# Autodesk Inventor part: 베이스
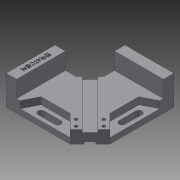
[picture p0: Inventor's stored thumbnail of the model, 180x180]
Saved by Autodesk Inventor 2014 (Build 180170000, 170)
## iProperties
Created: 2019-04
Part Number: 베이스
Material: Generic
Document SubType Name: Modeling
Designer: kh
Density: 1 g/cm^3
Appearance: Default
Author: kh
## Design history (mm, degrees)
sketch "Sketch1"
  geometry: L1 (-60, 60)-(60, 60); L2 (60, 60)-(60, -60); L3 (60, -60)-(-60, -60); L4 (-60, -60)-(-60, 60); L5 (-60, 60)-(60, -60); L6 (60, 60)-(-60, -60); L7 (60, -60)-(45.858, -45.858); L8 (45.858, -45.858)-(31.716, -60); L9 (45.858, -45.858)-(60, -31.716); 1 further point
  constraints: 18 end point, 3 equal length, 3 point on line, 2 midpoint, 2 perpendicular, 1 horizontal
  dimensions: "d5" = 120 distance of L2.end L3.end; "d6" = 120 distance of L1.end L2.end; "d7" = 20 distance of L2.end L7.end
extrude "Extrusion1" new body sketch "Sketch1" distance "d8" = 18; taper "d9" = 0 deg
sketch "Sketch2"
  geometry: L1 (-60, 60)-(-60, -60) reference; L2 (31.716, -60)-(60, -31.716) reference; L3 (60, 60)-(-60, 60) reference; L4 (45.858, -45.858)-(-19.903, 19.903); L5 (-60, 60)-(-60, 10); L6 (-60, 60)-(-10, 60); L7 (-19.903, 19.903)-(-44.384, -4.578); L8 (-19.903, 19.903)-(6.453, 46.259); L9 (-60, 10)-(-29.806, 10); L10 (-10, 60)-(-10, 29.806); 1 further point
  constraints: 14 end point, 4 point on line, 3 perpendicular, 1 collinear, 1 midpoint, 1 parallel
  dimensions: "d10" = 93 distance of L4.start L4.end; "d11" = 50 distance of L1.start L5.end; "d12" = 50 distance of L1.start L6.end
extrude "Extrusion2" cut sketch "Sketch2" stored distance "d13" = 18; taper "d14" = 0 deg
sketch "Sketch3"
  geometry: L1 (-29.806, 10)-(-60, 10) reference; L2 (60, -31.716)-(60, 60) reference; L3 (-60, -60)-(-45, -60); L4 (-45, -60)-(-45, 10); L5 (-45, 10)-(-60, 10); L6 (-60, 10)-(-60, -60); L7 (-10, 60)-(60, 60); L8 (60, 60)-(60, 45); L9 (60, 45)-(-10, 45); L10 (-10, 45)-(-10, 60); 1 further point
  constraints: 16 end point, 4 parallel, 2 horizontal, 2 perpendicular, 2 point on line
  dimensions: "d15" = 15 distance of L5.end L4.end; "d16" = 15 distance of L7.end L8.end
extrude "Extrusion3" join sketch "Sketch3" distance "d17" = 24; taper "d18" = 0 deg
sketch "Sketch4"
  geometry: L1 (31.716, -60)-(60, -31.716) reference; L2 (-10, 29.806)-(-29.806, 10) reference; L3 (-25.56, 14.246)-(40.201, -51.515); L4 (-14.246, 25.56)-(51.515, -40.201); L5 (0, 0)-(45.858, -45.858); L6 (-25.56, 14.246)-(-14.246, 25.56); L7 (40.201, -51.515)-(51.515, -40.201)
  constraints: 10 end point, 4 point on line, 2 perpendicular, 1 collinear, 1 midpoint, 1 parallel, 1 other
  dimensions: "d19" = 16 distance of L3.end L4.end
extrude "Extrusion4" cut sketch "Sketch4" distance "d20" = 3.5; taper "d21" = 0 deg
sketch "Sketch5"
  geometry: L1 (-31.716, -60)-(-60, -31.716) reference; L2 (29.806, 10)-(10, 29.806) reference; L3 (0, 0)-(-45.858, -45.858); L4 (-50.101, -41.615)-(15.66, 24.146); L5 (-41.615, -50.101)-(24.146, 15.66); L6 (15.66, 24.146)-(24.146, 15.66); L7 (-50.101, -41.615)-(-41.615, -50.101)
  constraints: 10 end point, 4 point on line, 2 collinear, 2 perpendicular, 1 midpoint, 1 other
  dimensions: "d22" = 12 distance of L4.start L5.start
extrude "Extrusion5" cut sketch "Sketch5" distance "d23" = 3; taper "d24" = 0 deg
sketch "Sketch6"
  geometry: L1 (-45, -60)-(31.716, -60) reference; L2 (31.716, -60)-(40.201, -51.515) reference; L3 (-45, -60)-(-40, -60); L4 (-40, -60)-(-30, -40); L5 (-30, -40)-(7.321, -40); L6 (31.716, -60)-(11.716, -40); L7 (-30, -40)-(11.716, -40); L8 (-60, 10)-(-60, -60) reference; L9 (-45, 10)-(-60, 10) reference; L10 (-60, 10)-(-60, -60) reference; L11 (-60, -60)-(-45, -60) reference; L12 (-45, -60)-(-45, 10) reference; L13 (-60, -60)-(-45, -60) reference; L14 (-20, -50)-(4, -50); L15 (-20, -52.25)-(4, -52.25); L16 (4, -47.75)-(-20, -47.75); L17 (-9.142, -40)-(-9.142, -60); A1 r 2.25 centre (-20, -50) between (-20, -47.75) and (-20, -52.25); A2 r 2.25 centre (4, -50) between (4, -52.25) and (4, -47.75); 2 further points
  constraints: 20 end point, 4 point on circle, 4 tangent, 3 parallel, 2 centre point, 2 midpoint, 2 perpendicular, 2 point on line, 1 collinear
  dimensions: "d25" = 5 distance of L1.start L3.end; "d26" = 30 horizontal distance of L4.end L8.end; "d30" = 20 vertical distance of L4.end L3.end; "d31" = 24 distance of L14.start L14.end; "d32" = 4.5 diameter of A2; "d33" = 40 horizontal distance of L14.start L8.end; "d34" = 10 vertical distance of L8.end L14.start
extrude "Extrusion6" cut sketch "Sketch6" distance "d35" = 10; taper "d36" = 0 deg
sketch "Sketch7"
  geometry: L1 (4, -47.75)-(-20, -47.75) reference; L2 (-20, -52.25)-(4, -52.25) reference; A1 r 2.25 centre (4, -50) between (4, -52.25) and (4, -47.75) reference; A2 r 2.25 centre (-20, -50) between (-20, -47.75) and (-20, -52.25) reference; 1 further point
extrude "Extrusion7" cut sketch "Sketch7" stored distance "d37" = 10; taper "d38" = 0 deg
sketch "Sketch8"
  geometry: L1 (60, -31.716)-(60, 45) reference; L2 (-10, 45)-(-10, 29.806) reference; L3 (-10, 29.806)-(-14.246, 25.56) reference; L4 (60, -31.716)-(40, -11.716); L5 (40, -11.716)-(40, 30); L6 (40, 30)-(60, 40); L7 (60, 45)-(60, 60) reference; L8 (60, 60)-(-10, 60) reference; L9 (-10, 60)-(-10, 45) reference; L10 (-10, 45)-(60, 45) reference; 1 further point
  constraints: 6 end point, 1 parallel, 1 perpendicular, 1 point on line
  dimensions: "d39" = 20 distance of L7.end L6.end; "d40" = 30 vertical distance of L5.end L7.end; "d41" = 20 horizontal distance of L5.end L7.end
extrude "Extrusion8" cut sketch "Sketch8" distance "d42" = 10; taper "d43" = 0 deg
sketch "Sketch9"
  geometry: L1 (60, 40)-(60, -31.716) reference; L2 (50, -4)-(50, 20); L3 (52.25, -4)-(52.25, 20); L4 (47.75, 20)-(47.75, -4); L5 (60, 45)-(60, 60) reference; L6 (60, 60)-(-10, 60) reference; L7 (-10, 60)-(-10, 45) reference; L8 (-10, 45)-(60, 45) reference; A1 r 2.25 centre (50, -4) between (47.75, -4) and (52.25, -4); A2 r 2.25 centre (50, 20) between (52.25, 20) and (47.75, 20); 2 further points
  constraints: 8 end point, 4 point on circle, 4 tangent, 2 centre point, 2 parallel, 1 midpoint
  dimensions: "d44" = 24 distance of L2.start L2.end; "d45" = 4.5 diameter of A2; "d46" = 40 vertical distance of L2.end L5.end; "d47" = 10 horizontal distance of L5.end L2.end
extrude "Extrusion9" cut sketch "Sketch9" stored distance "d48" = 10; taper "d49" = 0 deg
sketch "Sketch10"
  geometry: L1 (11.716, -40)-(31.716, -60) reference; L2 (31.716, -60)-(40.201, -51.515) reference; C1 r 2.25 at (31.716, -51.515); C2 r 2.25 at (23.23, -43.029); 1 further point
  constraints: 2 centre point
  dimensions: "d50" = 4.5 diameter of C1; "d51" = 4.5 diameter of C2; "d52" = 6 distance from line of C1.centre L2; "d53" = 6 distance from line of C1.centre L1; "d54" = 12 distance of C2.centre C1.centre; "d55" = 6 distance from line of C2.centre L1
extrude "Extrusion10" cut sketch "Sketch10" stored distance "d56" = 10; taper "d57" = 0 deg
sketch "Sketch11"
  geometry: L1 (-14.246, 25.56)-(51.515, -40.201) reference; L2 (51.515, -40.201)-(60, -31.716) reference; L3 (60, -31.716)-(40, -11.716) reference; C1 r 2.25 at (51.515, -31.716); C2 r 2.25 at (43.029, -23.23); 1 further point
  constraints: 2 centre point
  dimensions: "d58" = 4.5 diameter of C1; "d59" = 4.5 diameter of C2; "d60" = 6 distance from line of C1.centre L2; "d61" = 6 distance from line of C1.centre L3; "d62" = 12 distance of C1.centre C2.centre; "d63" = 6 distance from line of C2.centre L1
extrude "Extrusion11" cut sketch "Sketch11" stored distance "d64" = 10; taper "d65" = 0 deg
sketch "Sketch12"
  geometry: C1 r 2.25 at (-31.716, -51.515) reference; C2 r 2.25 at (-23.23, -43.029) reference; C3 r 4 at (-31.716, -51.515); C4 r 4 at (-23.23, -43.029); 1 further point
  constraints: 2 centre point, 2 coincident
  dimensions: "d66" = 8 diameter of C3; "d67" = 8 diameter of C4
extrude "Extrusion12" cut sketch "Sketch12" distance "d68" = 10; taper "d69" = 0 deg
sketch "Sketch13"
  geometry: C1 r 2.25 at (-51.515, -31.716) reference; C2 r 2.25 at (-43.029, -23.23) reference; C3 r 4 at (-51.515, -31.716); C4 r 4 at (-43.029, -23.23); 1 further point
  constraints: 2 centre point, 2 coincident
  dimensions: "d70" = 8 diameter of C3; "d71" = 8 diameter of C4
extrude "Extrusion13" cut sketch "Sketch13" distance "d72" = 10; taper "d73" = 0 deg
sketch "Sketch14"
  geometry: L1 (-20, -52.25)-(4, -52.25) reference; L2 (4, -47.75)-(-20, -47.75) reference; L3 (-20, -50)-(4, -50); L4 (-20, -54.5)-(4, -54.5); L5 (4, -45.5)-(-20, -45.5); A1 r 2.25 centre (4, -50) between (4, -52.25) and (4, -47.75) reference; A2 r 2.25 centre (-20, -50) between (-20, -47.75) and (-20, -52.25) reference; A3 r 4.5 centre (-20, -50) between (-20, -45.5) and (-20, -54.5); A4 r 4.5 centre (4, -50) between (4, -54.5) and (4, -45.5); 2 further points
  constraints: 8 end point, 4 point on circle, 4 tangent, 2 centre point, 2 parallel, 1 midpoint
  dimensions: "d74" = 9 distance between parallel lines of L4 L5
extrude "Extrusion14" cut sketch "Sketch14" stored distance "d75" = 10; taper "d76" = 0 deg
sketch "Sketch15"
  geometry: L1 (52.25, 20)-(52.25, -4) reference; L2 (47.75, -4)-(47.75, 20) reference; L3 (50, -4)-(50, 20); L4 (54.5, -4)-(54.5, 20); L5 (45.5, 20)-(45.5, -4); A1 r 2.25 centre (50, 20) between (52.25, 20) and (47.75, 20) reference; A2 r 2.25 centre (50, -4) between (47.75, -4) and (52.25, -4) reference; A3 r 4.5 centre (50, -4) between (45.5, -4) and (54.5, -4); A4 r 4.5 centre (50, 20) between (54.5, 20) and (45.5, 20); 2 further points
  constraints: 8 end point, 4 point on circle, 4 tangent, 2 centre point, 2 parallel, 1 midpoint
  dimensions: "d77" = 9 distance between parallel lines of L5 L4
extrude "Extrusion15" cut sketch "Sketch15" stored distance "d78" = 10; taper "d79" = 0 deg
sketch "Sketch16"
  geometry: L1 (-45, 10)-(-60, 10) reference; L2 (-45, -60)-(-45, 10) reference; L3 (-49.498, -4.261)-(-49.498, -45.739); L4 (-49.498, -45.739)-(-55.502, -45.739); L5 (-55.502, -45.739)-(-55.502, -4.261); L6 (-55.502, -4.261)-(-49.498, -4.261); L7 (-49.498, -4.261)-(-55.502, -45.739); 2 further points
  constraints: 2 end point, 1 midpoint, 2 other
  dimensions: "d80" = 35 distance from line of L1 point (-52.5, -25); "d81" = 7.5 distance from line of point (-52.5, -25) L2
emboss "Emboss1" sketch "Sketch16" dims "d10" = 93, "d11" = 50, "d12" = 50, "d82" = 0.5, "d83" = 0
body "Solid1"
node "Projected Loop1"
node "Projected Loop2"
node "Projected Loop3"
